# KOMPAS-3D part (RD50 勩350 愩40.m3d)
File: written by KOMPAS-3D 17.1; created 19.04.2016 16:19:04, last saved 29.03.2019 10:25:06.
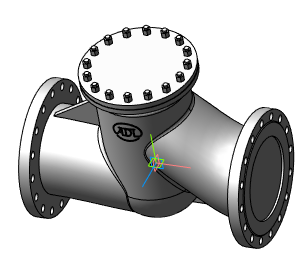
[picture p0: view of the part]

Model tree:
1. Операция без истории:2  (labels: Сталь 20  ГОСТ 1050-88)

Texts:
  RD50 Ду15 Ру40
  RD50 Ду20 Ру40
  RD50 Ду25 Ру40
  RD50 Ду32 Ру40
  RD50 Ду40 Ру40
  RD50 Ду50 Ру40
  RD50 Ду65 Ру40
  RD50 Ду80 Ру40
  RD50 Ду100 Ру40
  RD50 Ду125 Ру40
  RD50 Ду150 Ру40
  RD50 Ду200 Ру40
  RD50 Ду250 Ру40
  RD50 Ду300 Ру40
  RD50 Ду350 Ру40
  RD50 Ду400 Ру40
